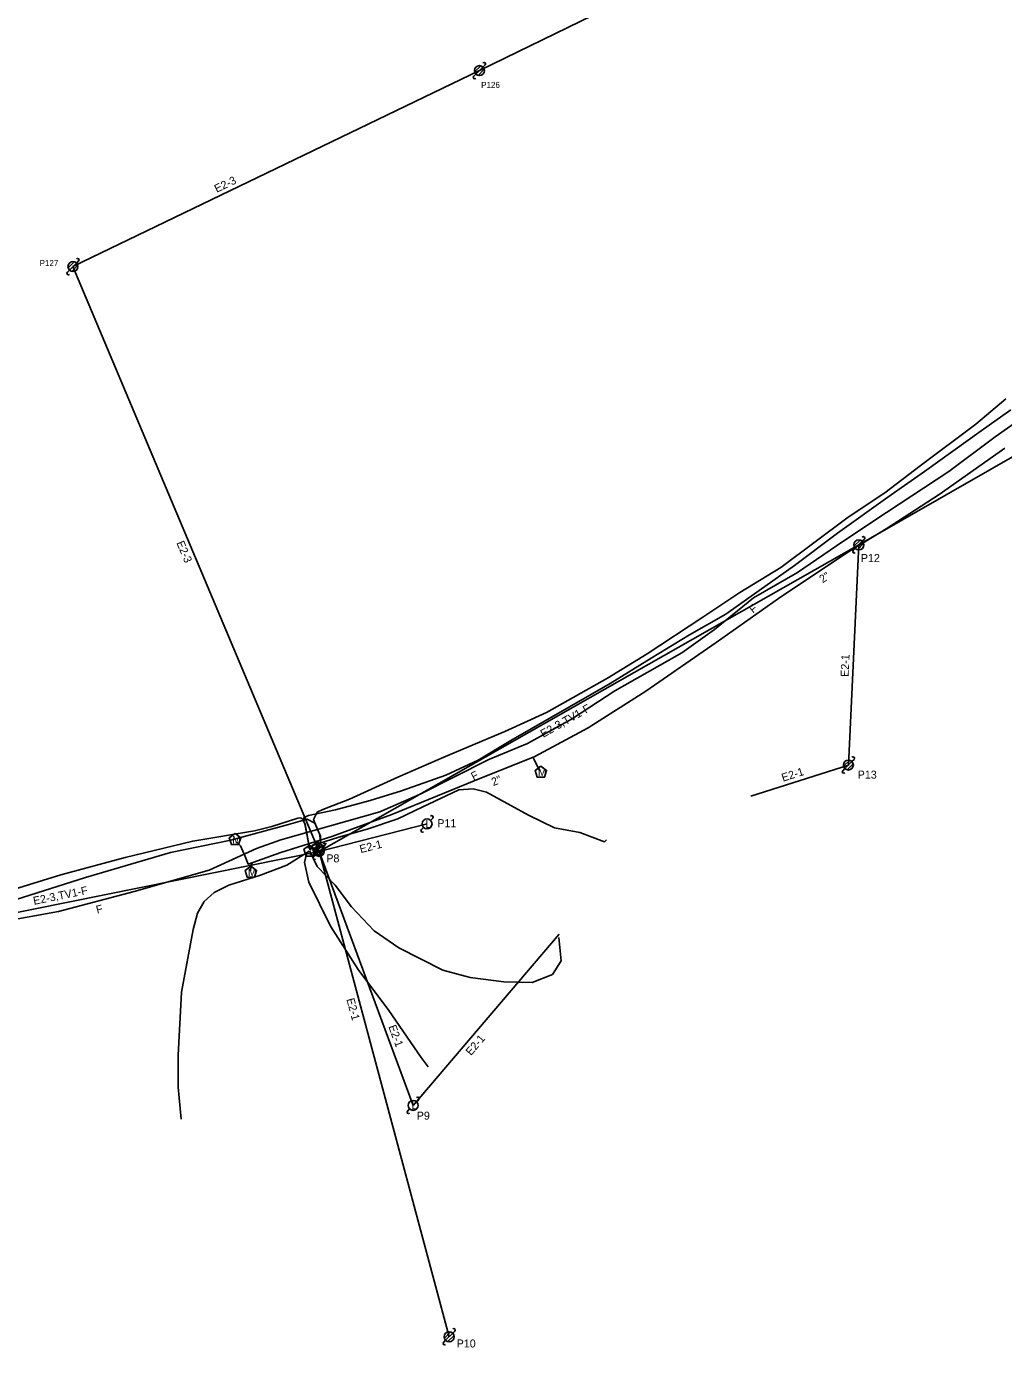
# Model space of a CAD drawing. Extents: x 1741604 to 1825760, y 1164229 to 1194908.
# Drawn here: x 1754446 to 1754935, y 1168303 to 1168963 of the extents above; entities that cross this region are included whole.
import ezdxf

# ---------------------------------------------------------------- set-up
doc = ezdxf.new("R2010")
doc.units = 0
for name, color, linetype in [('RD_EX_SU_H2O', 7, 'Continuous'), ('RD_EX_SU_Ovhd', 7, 'Continuous'), ('RD_EX_SU_Pole', 7, 'Continuous'), ('RD_EX_SU_Telecom', 7, 'Continuous'), ('RD_EX_SU_TX_H2O', 7, 'Continuous'), ('RD_EX_SU_TX_Pole', 7, 'Continuous'), ('RD_EX_SU_TX_Telecom', 7, 'Continuous')]:
    doc.layers.add(name, color=color, linetype=linetype)

msp = doc.modelspace()

# ---------------------------------------------------------------- linework, layer by layer
at = {"layer": 'RD_EX_SU_H2O'}
msp.add_line((1754699.54, 1168597.66), (1754703.04, 1168590.84), dxfattribs=at)
for points in [[(1754902.54, 1168728.95), (1754935.35, 1168752.07)], [(1754551.4, 1168555.27), (1754553.45, 1168553.26), (1754555.69, 1168548.06), (1754557.26, 1168544.12), (1754573.61, 1168549.98), (1754599.05, 1168558.06), (1754628.96, 1168568.94), (1754670.14, 1168585.77), (1754700.55, 1168598.07), (1754727.06, 1168612.33), (1754755.98, 1168630.73), (1754791.02, 1168654.94), (1754822.19, 1168677.03), (1754856.39, 1168699.78), (1754876.03, 1168711.79), (1754902.54, 1168728.95)], [(1754558.37, 1168540.81), (1754558.59, 1168542.73), (1754559.26, 1168544.84)]]:
    msp.add_lwpolyline(points, dxfattribs=at)
for points in [[(1754703.49, 1168593.16), (1754700.59, 1168591.05), (1754701.69, 1168587.64), (1754705.28, 1168587.64), (1754706.39, 1168591.05)], [(1754550.69, 1168559.5), (1754547.78, 1168557.39), (1754548.89, 1168553.98), (1754552.48, 1168553.98), (1754553.59, 1168557.39)], [(1754558.58, 1168543.14), (1754555.68, 1168541.03), (1754556.78, 1168537.62), (1754560.37, 1168537.62), (1754561.48, 1168541.03)]]:
    msp.add_lwpolyline(points, close=True, dxfattribs=at)
at = {"layer": 'RD_EX_SU_Ovhd'}
for p, q in [((1754672.78, 1168940.82), (1754875.27, 1169039.79)), ((1754469.71, 1168842.87), (1754672.78, 1168940.82)), ((1754469.71, 1168842.87), (1754592.73, 1168550.59)), ((1754862.36, 1168703.77), (1755054.51, 1168814.05)), ((1754592.73, 1168550.59), (1754862.36, 1168703.77)), ((1754857.15, 1168593.74), (1754862.36, 1168703.77)), ((1754808.45, 1168578.13), (1754857.15, 1168593.74)), ((1754592.73, 1168550.59), (1754646.62, 1168564.31)), ((1754196.86, 1168470.58), (1754592.73, 1168550.59)), ((1754592.73, 1168550.59), (1754639.65, 1168423.62)), ((1754592.73, 1168550.59), (1754657.67, 1168307.97)), ((1754639.65, 1168423.62), (1754712.71, 1168509.14))]:
    msp.add_line(p, q, dxfattribs=at)
at = {"layer": 'RD_EX_SU_Pole'}
for p, q in [((1754674.55, 1168942.59), (1754675.61, 1168943.65)), ((1754669.96, 1168937.99), (1754671.02, 1168939.05)), ((1754670.37, 1168940.17), (1754673.43, 1168943.24)), ((1754671.02, 1168939.05), (1754674.55, 1168942.59)), ((1754672.14, 1168938.41), (1754675.2, 1168941.47)), ((1754467.3, 1168842.22), (1754470.36, 1168845.29)), ((1754467.95, 1168841.1), (1754471.48, 1168844.64)), ((1754471.48, 1168844.64), (1754472.54, 1168845.7)), ((1754466.89, 1168840.04), (1754467.95, 1168841.1)), ((1754469.07, 1168840.46), (1754472.13, 1168843.52)), ((1754859.94, 1168703.12), (1754863, 1168706.18)), ((1754864.12, 1168705.54), (1754865.18, 1168706.6)), ((1754859.53, 1168700.94), (1754860.59, 1168702)), ((1754860.59, 1168702), (1754864.12, 1168705.54)), ((1754861.71, 1168701.35), (1754864.77, 1168704.42)), ((1754854.73, 1168593.09), (1754857.8, 1168596.15)), ((1754855.38, 1168591.97), (1754858.92, 1168595.5)), ((1754856.5, 1168591.32), (1754859.56, 1168594.38)), ((1754858.92, 1168595.5), (1754859.98, 1168596.56)), ((1754854.32, 1168590.91), (1754855.38, 1168591.97)), ((1754648.39, 1168566.08), (1754649.45, 1168567.14)), ((1754643.79, 1168561.48), (1754644.85, 1168562.54)), ((1754589.9, 1168547.77), (1754590.97, 1168548.83)), ((1754590.32, 1168549.95), (1754593.38, 1168553.01)), ((1754590.97, 1168548.83), (1754594.5, 1168552.36)), ((1754592.09, 1168548.18), (1754595.15, 1168551.24)), ((1754594.5, 1168552.36), (1754595.56, 1168553.42)), ((1754636.83, 1168420.79), (1754637.89, 1168421.85)), ((1754641.42, 1168425.38), (1754642.48, 1168426.44)), ((1754655.26, 1168307.32), (1754658.32, 1168310.39)), ((1754655.91, 1168306.2), (1754659.44, 1168309.74)), ((1754659.44, 1168309.74), (1754660.5, 1168310.8)), ((1754654.84, 1168305.14), (1754655.91, 1168306.2)), ((1754657.03, 1168305.56), (1754660.09, 1168308.62))]:
    msp.add_line(p, q, dxfattribs=at)
for centre in [(1754672.78, 1168940.82), (1754469.71, 1168842.87), (1754862.36, 1168703.77), (1754857.15, 1168593.74), (1754646.62, 1168564.31), (1754592.73, 1168550.59), (1754639.65, 1168423.62), (1754657.67, 1168307.97)]:
    msp.add_circle(centre, 2.5, dxfattribs=at)
for centre, start, end in [((1754675.08, 1168944.18), 315, 135), ((1754670.49, 1168937.46), 135, 315), ((1754472.01, 1168846.23), 315, 135), ((1754467.42, 1168839.51), 135, 315), ((1754864.65, 1168707.13), 315, 135), ((1754860.06, 1168700.41), 135, 315), ((1754859.45, 1168597.09), 315, 135), ((1754854.85, 1168590.38), 135, 315), ((1754648.92, 1168567.67), 315, 135), ((1754644.32, 1168560.95), 135, 315), ((1754595.03, 1168553.95), 315, 135), ((1754590.43, 1168547.24), 135, 315), ((1754641.95, 1168426.97), 315, 135), ((1754637.36, 1168420.26), 135, 315), ((1754659.97, 1168311.33), 315, 135), ((1754655.38, 1168304.61), 135, 315)]:
    msp.add_arc(centre, 0.75, start, end, dxfattribs=at)
at = {"layer": 'RD_EX_SU_Telecom'}
for p, q in [((1754590.43, 1168550.98), (1754593.24, 1168553.79)), ((1754594.68, 1168553.08), (1754596.33, 1168554.74)), ((1754589.49, 1168547.89), (1754591.14, 1168549.54)), ((1754590.81, 1168549.95), (1754594.27, 1168553.41)), ((1754591.51, 1168549.24), (1754594.99, 1168552.71)), ((1754591.61, 1168552.09), (1754591.75, 1168549.98)), ((1754592.53, 1168548.84), (1754595.38, 1168551.69)), ((1754594.43, 1168549.33), (1754594.9, 1168549.79))]:
    msp.add_line(p, q, dxfattribs=at)
for points in [[(1754431.02, 1168514.93), (1754462.47, 1168520.45), (1754500.35, 1168530.47), (1754537.76, 1168541.24), (1754561.32, 1168551.95), (1754573.48, 1168556.35), (1754623.02, 1168570.27), (1754642.92, 1168579.07), (1754677.47, 1168596.56), (1754696.82, 1168604.43), (1754718.75, 1168616.63), (1754740.5, 1168630.89), (1754773.95, 1168649.84), (1754790.22, 1168661.42), (1754809.76, 1168677.24), (1754831.74, 1168690.04), (1754854.43, 1168705.48), (1754876.15, 1168720.01), (1754907.28, 1168740.45), (1754930.49, 1168757.72), (1754969.72, 1168785.32)], [(1754592.14, 1168552.7), (1754593.3, 1168554.75), (1754593.03, 1168558.8), (1754590.52, 1168564.83), (1754589.93, 1168566.52), (1754591.66, 1168570.21), (1754594.61, 1168571.54), (1754607.93, 1168576.6), (1754632.02, 1168587.64), (1754654.98, 1168597.6), (1754685.55, 1168610.56), (1754706.35, 1168620.02), (1754736.84, 1168637.14), (1754756.57, 1168649.23), (1754784.4, 1168667.59), (1754802.99, 1168680.02), (1754823.35, 1168692.41), (1754857, 1168717.63), (1754875.4, 1168729.85), (1754893.02, 1168743.21), (1754920.83, 1168764.1), (1754935.86, 1168776.74)], [(1754588.04, 1168551.32), (1754585.68, 1168564.07), (1754585.09, 1168565.54), (1754585, 1168567.44), (1754587.45, 1168568.53), (1754600.85, 1168571.31), (1754618.14, 1168575.97), (1754633.85, 1168580.9), (1754656.07, 1168588.6), (1754672.12, 1168596.17), (1754688.57, 1168606.01), (1754707.58, 1168616.98), (1754738.16, 1168634.54), (1754758.69, 1168647.15), (1754777.79, 1168658.79), (1754795.97, 1168669.19), (1754812.53, 1168680.96), (1754830.18, 1168693.49), (1754851.64, 1168709.62), (1754876.85, 1168727.65), (1754895.21, 1168740.49), (1754923.58, 1168760.84), (1754938.29, 1168771.31)], [(1754588.42, 1168551.31), (1754589.39, 1168553.53), (1754602.57, 1168557.62), (1754616.75, 1168561.71), (1754632, 1168566.86), (1754644.58, 1168572.86), (1754662.53, 1168581.3), (1754669.64, 1168581.88), (1754676.3, 1168580.23), (1754697.29, 1168568.67), (1754710.28, 1168562.42), (1754722.97, 1168559.96), (1754735.31, 1168555.4), (1754736.33, 1168556.28)], [(1754236.22, 1168431.65), (1754230.33, 1168444.31), (1754230.04, 1168445.95), (1754231.64, 1168447.42), (1754256.51, 1168459.77), (1754296.78, 1168478.31), (1754327.18, 1168491.13), (1754359.65, 1168503.93), (1754392.06, 1168515.93), (1754422.05, 1168526.09), (1754463.64, 1168538.92), (1754495.81, 1168547.57), (1754529.51, 1168555.73), (1754560.42, 1168560.9), (1754569.04, 1168563.04), (1754582.1, 1168567.2), (1754583.53, 1168567.3), (1754584.36, 1168566.64), (1754585.53, 1168564.26), (1754588.01, 1168551.37)], [(1754441.29, 1168526.45), (1754475.98, 1168537.52), (1754518.45, 1168549.94), (1754548.55, 1168556.09), (1754577.36, 1168564.06), (1754586.66, 1168566.69), (1754590.58, 1168564.62), (1754593.31, 1168558.1), (1754593.37, 1168554.77), (1754592.04, 1168552.62)], [(1754523.8, 1168416.74), (1754522.19, 1168432.79), (1754522.31, 1168448.7), (1754523.88, 1168480.24), (1754529.73, 1168511.51), (1754531.88, 1168519.74), (1754535.31, 1168525.56), (1754540.27, 1168530.01), (1754547.5, 1168533.69), (1754563.48, 1168538.63), (1754576.49, 1168543.71), (1754587.64, 1168550.72)], [(1754587.68, 1168550.6), (1754586.31, 1168549.26), (1754585.35, 1168544.98), (1754587.53, 1168535.25), (1754598.44, 1168513.23), (1754612.23, 1168491.46), (1754627.57, 1168471.06), (1754643.65, 1168447.5), (1754647.14, 1168442.95)], [(1754588.24, 1168550.41), (1754591.71, 1168543.03), (1754600.75, 1168533.64), (1754608.81, 1168522.83), (1754620.2, 1168510.91), (1754632.52, 1168502.32), (1754654.56, 1168491.26), (1754668.16, 1168487.53), (1754684.95, 1168485.3), (1754699.23, 1168485.03), (1754709.3, 1168489.01), (1754713.62, 1168495.83), (1754712.51, 1168507.6)]]:
    msp.add_lwpolyline(points, dxfattribs=at)
for points in [[(1754587.95, 1168553.67), (1754585.1, 1168551.6), (1754586.19, 1168548.25), (1754589.71, 1168548.25), (1754590.8, 1168551.6)], [(1754591.89, 1168555.37), (1754589.03, 1168553.3), (1754590.12, 1168549.95), (1754593.65, 1168549.95), (1754594.74, 1168553.3)]]:
    msp.add_lwpolyline(points, close=True, dxfattribs=at)
msp.add_circle((1754592.91, 1168551.31), 2.5, dxfattribs=at)

# ---------------------------------------------------------------- texts
at = {"layer": 'RD_EX_SU_H2O'}
for p in [(1754702.05, 1168588.23), (1754549.25, 1168554.58), (1754557.14, 1168538.22)]:
    msp.add_text('M', height=3.75, dxfattribs=at).set_placement(p)
at = {"layer": 'RD_EX_SU_Ovhd'}
for s, rotation, p in [('E2-3', 25.74998, (1754541.53, 1168879.73)), ('E2-3', 292.82611, (1754521.32, 1168704.78)), ('E2-1', 87.29059, (1754857.23, 1168637.7)), ('E2-3,TV1-F', 29.60119, (1754704.67, 1168607.28)), ('E2-1', 17.76297, (1754824.49, 1168585.37)), ('E2-1', 14.27998, (1754613.48, 1168549.68)), ('E2-3,TV1-F', 11.42718, (1754450.23, 1168523.83)), ('E2-1', 284.98443, (1754606.31, 1168476.65)), ('E2-1', 290.28018, (1754627.24, 1168462.99)), ('E2-1', 49.49571, (1754668.57, 1168448.23))]:
    msp.add_text(s, height=4, rotation=rotation, dxfattribs=at).set_placement(p)
at = {"layer": 'RD_EX_SU_Pole'}
for p in [(1754645.76, 1168562.31), (1754638.79, 1168421.62)]:
    msp.add_text('L', height=4, dxfattribs=at).set_placement(p)
at = {"layer": 'RD_EX_SU_Telecom'}
for p in [(1754590.63, 1168550.5), (1754586.69, 1168548.8)]:
    msp.add_text('T', height=3.75, dxfattribs=at).set_placement(p)
at = {"layer": 'RD_EX_SU_TX_H2O'}
for rotation, p in [(33.61756, (1754844.27, 1168684.51)), (22.03203, (1754679.73, 1168583.17))]:
    msp.add_text('2"', height=4, rotation=rotation, dxfattribs=at).set_placement(p)
at = {"layer": 'RD_EX_SU_TX_Pole'}
for s, height, p in [('P126', 3, (1754673.65, 1168932.18)), ('P127', 3, (1754453.03, 1168843.13)), ('P12', 4, (1754863.37, 1168695.19)), ('P13', 4, (1754861.8, 1168586.93)), ('P11', 4, (1754651.74, 1168562.67)), ('P8', 4, (1754596.28, 1168545.1)), ('P9', 4, (1754641.48, 1168416.48)), ('P10', 4, (1754661.42, 1168302.61))]:
    msp.add_text(s, height=height, dxfattribs=at).set_placement(p)
at = {"layer": 'RD_EX_SU_TX_Telecom'}
for rotation, p in [(39.00643, (1754809.52, 1168669.33)), (26.84775, (1754669.81, 1168585.96)), (14.81684, (1754481.82, 1168519.36))]:
    msp.add_text('F', height=4, rotation=rotation, dxfattribs=at).set_placement(p)

doc.saveas('drawing.dxf')
